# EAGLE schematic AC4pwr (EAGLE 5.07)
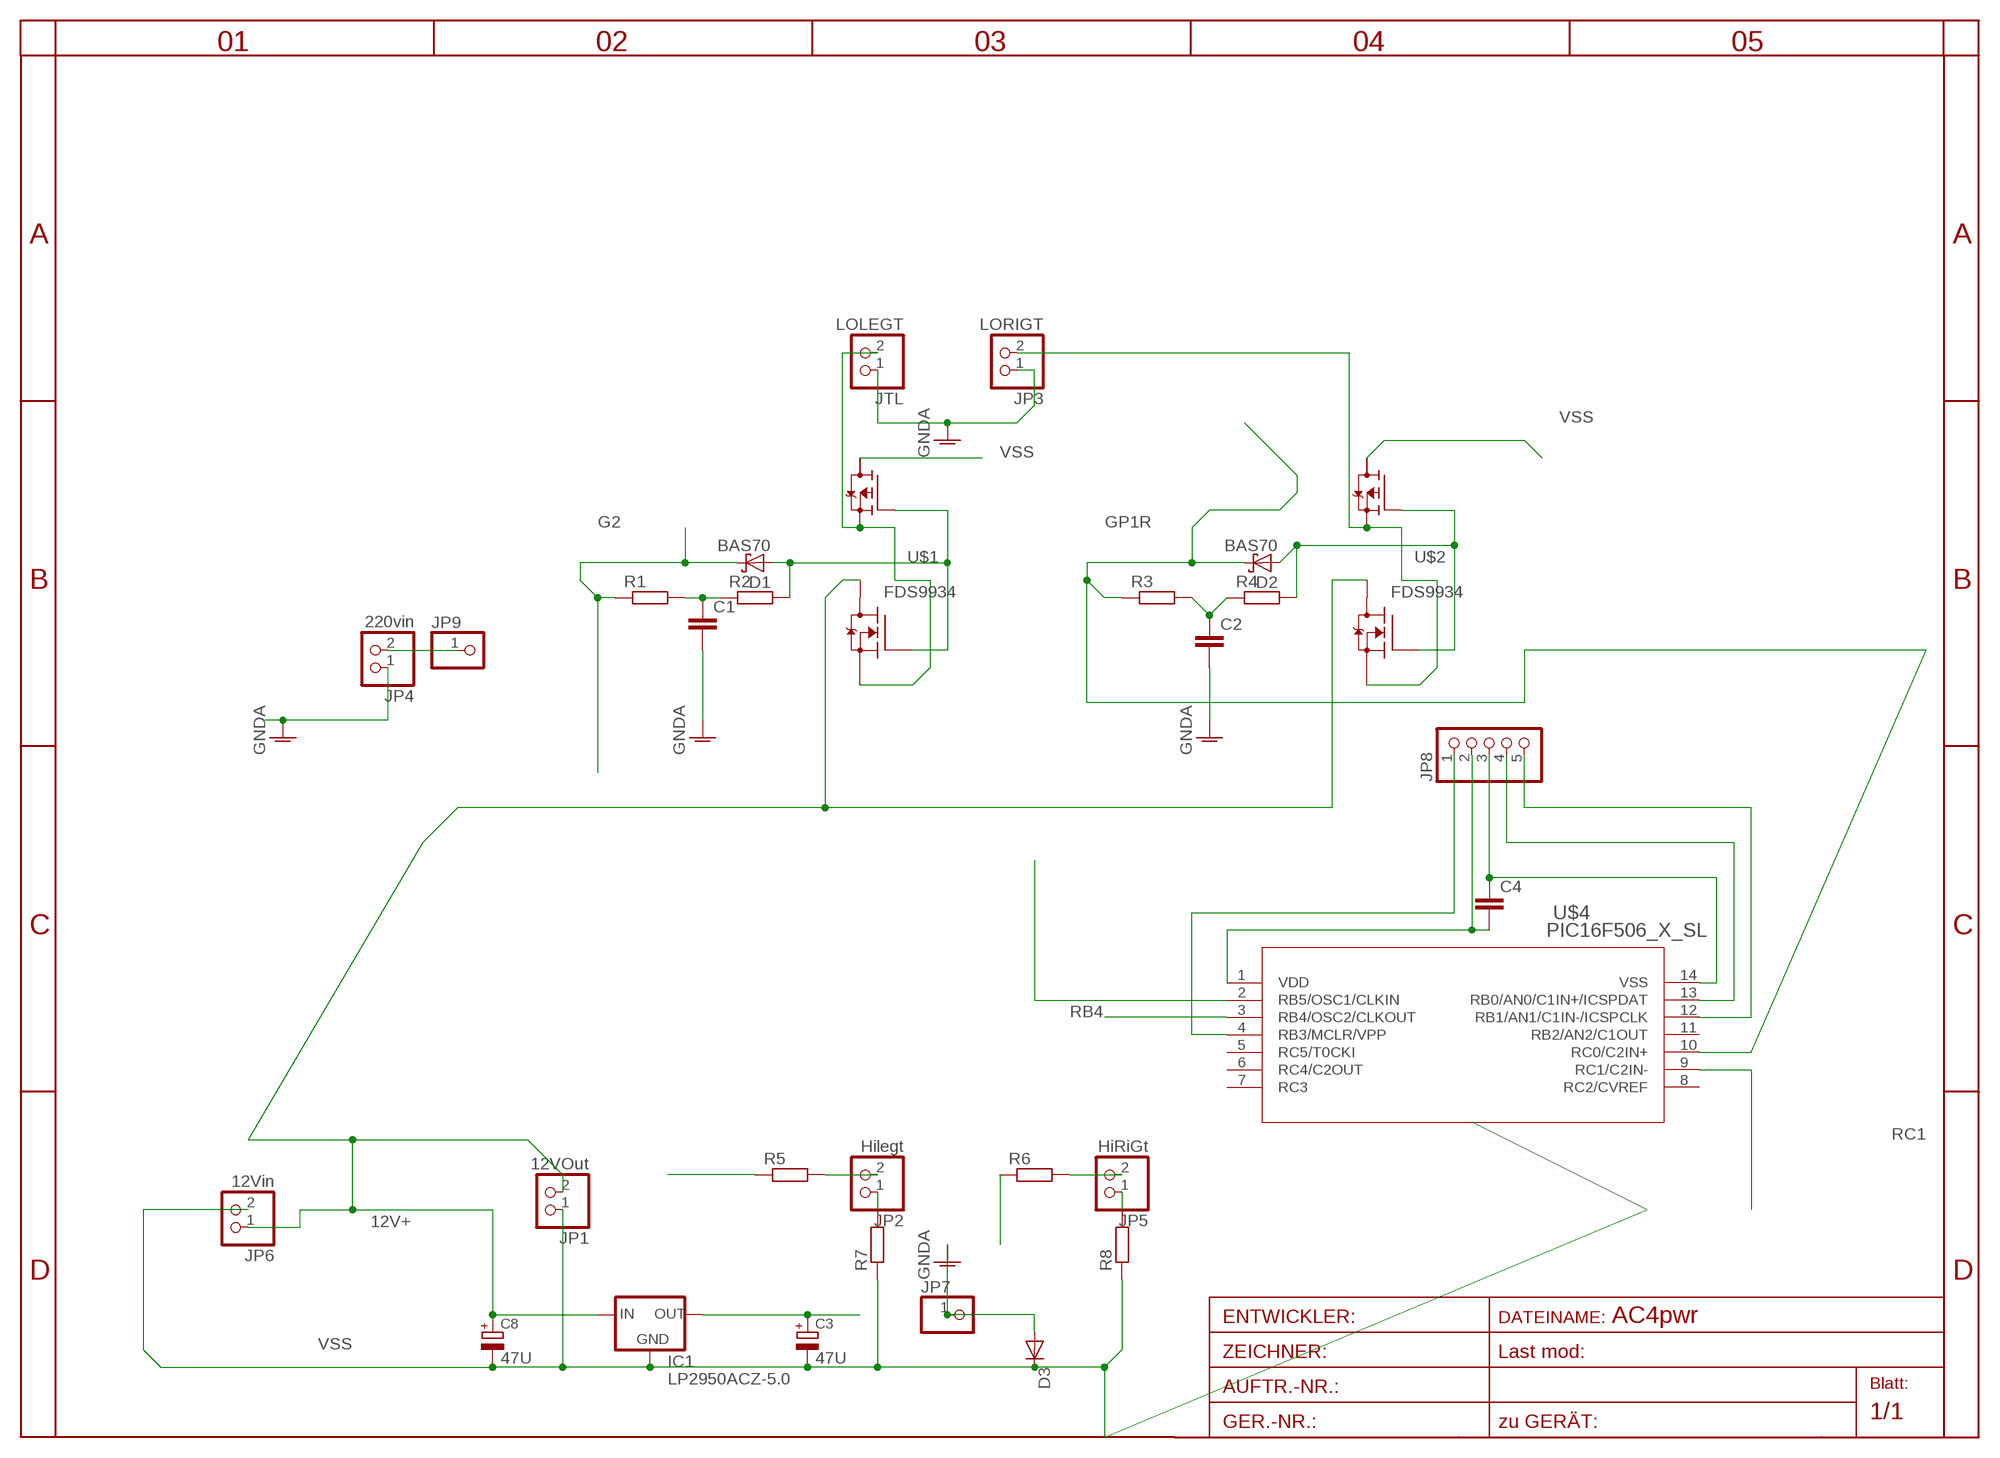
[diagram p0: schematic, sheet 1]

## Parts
C1  C-EUC0805  [C0805]
C2  C-EUC0805  [C0805]
C3  47U  CPOL-EUE5-5  [E5-5]
C4  C-EUC0805  [C0805]
C8  47U  CPOL-EUE5-5  [E5-5]
D1  BAS70  [SOT23]
D2  BAS70  [SOT23]
D3  DIODE-MINIMELF  [MINIMELF]
IC1  LP2950ACZ-5.0  [TO92]
JP1  12VOut  PINHD-1X2STR  [1X02]
JP2  Hilegt  PINHD-1X2STR  [1X02]
JP3  LORIGT  PINHD-1X2STR  [1X02]
JP4  220vin  PINHD-1X2STR  [1X02]
JP5  HiRiGt  PINHD-1X2STR  [1X02]
JP6  12Vin  PINHD-1X2STR  [1X02]
JP7  PINHD-1X13MM2  [1X3MM2]
JP8  PINHD-1X5/90  [1X05/90]
JP9  PINHD-1X13MM2  [1X3MM2]
JTL  LOLEGT  PINHD-1X2STR  [1X02]
R1  R-EU_M0805  [M0805]
R2  R-EU_M0805  [M0805]
R3  R-EU_M0805  [M0805]
R4  R-EU_M0805  [M0805]
R5  R-EU_M0805  [M0805]
R6  R-EU_M0805  [M0805]
R7  R-EU_M0805  [M0805]
R8  R-EU_M0805  [M0805]
U$1  FDS9934  [SO-8]
U$2  FDS9934  [SO-8]
U$4  PIC16F506_X_SL  [SOIC14_N_MC]

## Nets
12V+: C8.+ IC1.3(IN) JP1.2 JP6.1 U$1.7(Q1D2) U$2.7(Q1D2)
G2: D1.3(C) R1.1
GNDA: C1.2 C2.2 D3.A JP3.1 JP4.1 JP7.1 JTL.1
GP1R: D2.3(C) R3.1 U$4.10(RC0/C2IN+)
GP2R: D1.1(A) R2.2 U$1.2(Q1G) U$1.4(Q2G)
GP2R1: D2.1(A) R4.2 U$2.2(Q1G) U$2.4(Q2G)
N$1: C1.1 R1.2 R2.1
N$2: JP3.2 U$2.1(Q1S) U$2.3(Q2S)
N$3: C2.1 R3.2 R4.1
N$4: JTL.2 U$1.1(Q1S) U$1.3(Q2S)
N$5: JP8.1 U$4.4(RB3/MCLR/VPP)
N$6: JP4.2 JP9.1
N$7: JP8.5 U$4.12(RB1/AN1/C1IN-/ICSPCLK)
N$8: JP5.2 R6.2
N$9: JP5.1 R8.2
N$10: C4.1 JP8.3 U$4.14(VSS)
N$11: JP2.1 R7.2
N$12: JP2.2 R5.2
N$13: JP8.4 U$4.13(RB0/AN0/C1IN+/ICSPDAT)
N$14: U$4.2(RB5/OSC1/CLKIN)
RB4: R5.1 U$4.3(RB4/OSC2/CLKOUT)
RC1: R6.1 U$4.9(RC1/C2IN-)
VDD: C3.+ C4.2 IC1.1(OUT) JP8.2 U$4.1(VDD)
VSS: C3.- C8.- D3.C IC1.2(GND) JP1.1 JP6.2 R7.1 R8.1 U$1.5(Q2D2) U$2.5(Q2D2)
Unconnected: U$1.6(Q2D) U$1.8(Q1D1) U$2.6(Q2D) U$2.8(Q1D1) U$4.5(RC5/T0CKI) U$4.6(RC4/C2OUT) U$4.7(RC3) U$4.8(RC2/CVREF) U$4.11(RB2/AN2/C1OUT)

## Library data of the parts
C1 C2 C4 = rcl:C-EU: CAPACITOR, European symbol
C3 C8 = rcl-2:CPOL-EU: POLARIZED CAPACITOR, European symbol
D1 D2 = diode:BAS70: Silicon Schottky Diodes
D3 = diode:DIODE-: DIODE
IC1 = v-reg:LP2950?*: Source: http://cache.national.com/ds/LP/LP2950.pdf
JP1-JP6 JTL = pinhead:PINHD-1X2: PIN HEADER
JP7 JP9 = pinhead:PINHD-1X1: PIN HEADER
JP8 = pinhead:PINHD-1X5: PIN HEADER
R1-R8 = rcl:R-EU_: RESISTOR, European symbol
U$1 U$2 = transistor-fet:FDS9934
U$4 = pic16f506mc:PIC16F506_X_SL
